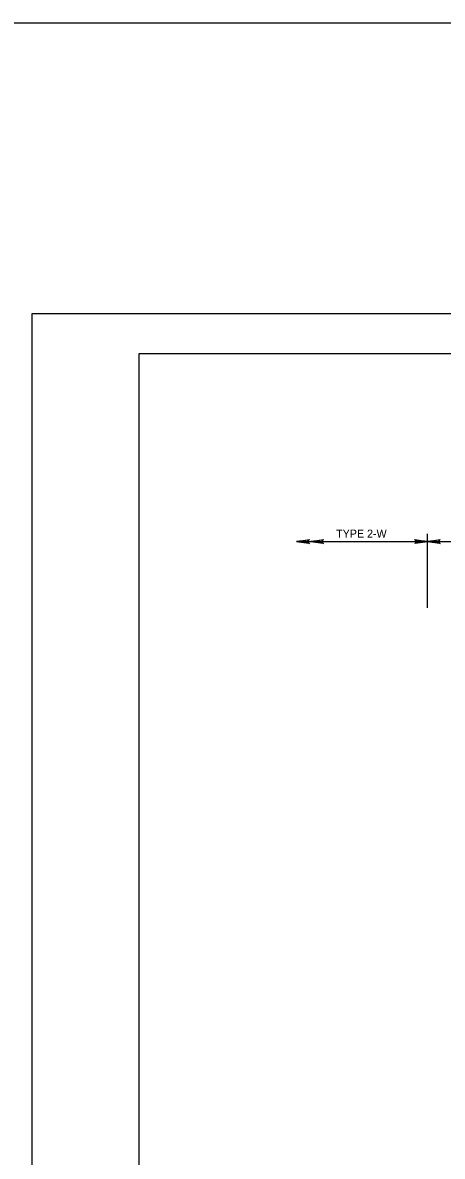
# Model space of a CAD drawing. Extents: x 637628 to 640188, y 298266 to 300751.
# Drawn here: x 639116 to 639273.5, y 300325.7 to 300750.7 of the extents above; entities that cross this region are included whole.
import ezdxf

# ---------------------------------------------------------------- set-up
doc = ezdxf.new("R2010")
doc.units = 0
for name, color, linetype in [('1', 7, 'Continuous'), ('2', 7, 'Continuous'), ('S-ABUT-CONC', 7, 'Continuous')]:
    doc.layers.add(name, color=color, linetype=linetype)

msp = doc.modelspace()

# ---------------------------------------------------------------- linework, layer by layer
at = {"layer": '1'}
msp.add_lwpolyline([(639119.52, 300641.58), (639960.52, 300641.58), (639960.52, 300047.58), (639119.52, 300047.58)], close=True, dxfattribs=at)
msp.add_lwpolyline([(639945.52, 300062.58), (639945.52, 300626.55), (639159.55, 300626.55), (639159.55, 300062.58), (639945.52, 300062.58), (639945.52, 300088.93), (639745.53, 300088.93), (639745.53, 300153.61), (639945.52, 300153.61), (639945.52, 300182.57), (639745.53, 300182.57), (639745.53, 300062.58), (639824.33, 300062.58), (639824.33, 300088.93), (639824.33, 300062.58), (639901.33, 300062.58), (639901.33, 300088.93), (639901.33, 300076.62), (639945.52, 300076.62)], dxfattribs=at)
at = {"layer": '2'}
msp.add_lwpolyline([(638881.69, 300750.65), (640188.06, 300750.65), (640188.06, 299900.76), (638881.69, 299900.76)], close=True, dxfattribs=at)
for points in [[(639223.37, 300555.56), (639223.2, 300555.89), (639218.83, 300556.12), (639223.37, 300555.56), (639223.6, 300555.36), (639218.83, 300556.12), (639223.2, 300556.34), (639223.36, 300556.67), (639218.83, 300556.12), (639223.6, 300556.89), (639223.36, 300556.67)], [(639228.66, 300555.56), (639228.49, 300555.89), (639224.12, 300556.12), (639228.66, 300555.56), (639228.89, 300555.36), (639224.12, 300556.12), (639228.49, 300556.34), (639228.65, 300556.67), (639224.12, 300556.12), (639228.89, 300556.89), (639228.65, 300556.67)], [(639263.36, 300556.69), (639263.53, 300556.36), (639267.9, 300556.12), (639263.36, 300556.69), (639263.13, 300556.89), (639267.9, 300556.12), (639263.53, 300555.91), (639263.37, 300555.58), (639267.9, 300556.12), (639263.13, 300555.36), (639263.37, 300555.58)], [(639272.44, 300555.56), (639272.27, 300555.89), (639267.9, 300556.12), (639272.44, 300555.56), (639272.67, 300555.36), (639267.9, 300556.12), (639272.27, 300556.34), (639272.43, 300556.67), (639267.9, 300556.12), (639272.67, 300556.89), (639272.43, 300556.67)]]:
    msp.add_lwpolyline(points, dxfattribs=at)
at = {"layer": 'S-ABUT-CONC'}
for p, q in [((639267.9, 300531.31), (639267.9, 300559.09)), ((639218.83, 300556.12), (639267.9, 300556.12)), ((639267.9, 300556.12), (639311.68, 300556.12))]:
    msp.add_line(p, q, dxfattribs=at)

# ---------------------------------------------------------------- texts
msp.add_text('TYPE 2-W', height=3, dxfattribs=at).set_placement((639233.67, 300557.62))

doc.saveas('drawing.dxf')
